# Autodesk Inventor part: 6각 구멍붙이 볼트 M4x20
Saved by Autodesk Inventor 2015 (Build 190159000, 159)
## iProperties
Created: 2026-05
Part Number: 6각 구멍붙이 볼트 M4x20
Material: 일반
Document SubType Name: Modeling
Designer: 104
Density: 1 g/cm^3
Appearance: 기본값
Author: 104
Author: jhkim
Description: 6각머리 태핑 나사
Creation Date: 2026-04-27
Sending System: Autodesk Inventor 2027
Preprocessor: ST-DEVELOPER v20.1
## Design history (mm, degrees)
node "6각 구멍붙이 볼트 M4x201"
body "Solid1"
node "기준1"
